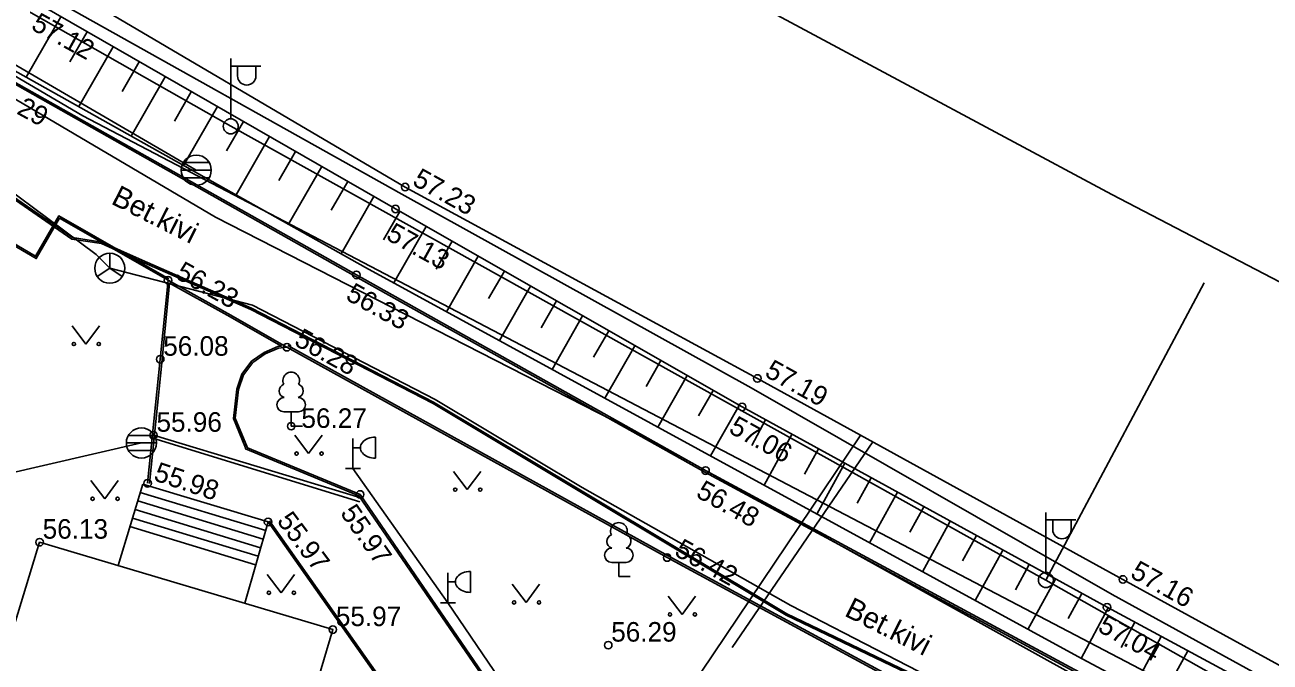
# Model space of a CAD drawing. Extents: x 542320 to 543602, y 6558748 to 6559969.
# Drawn here: x 543038.66 to 543080.07, y 6558919.22 to 6558940.4 of the extents above; entities that cross this region are included whole.
import ezdxf

# ---------------------------------------------------------------- set-up
doc = ezdxf.new("R2010")
doc.units = 0
for name, color, linetype in [('HALJASTUS', 7, 'Continuous'), ('HOONE', 7, 'Continuous'), ('HOONEDET', 7, 'Continuous'), ('KORGUS-EH2000', 7, 'Continuous'), ('KTRASS', 7, 'Continuous'), ('mootpiir', 7, 'Continuous'), ('MPKAABEL', 7, 'Continuous'), ('MPOHULIIN', 7, 'Continuous'), ('PIIR', 7, 'Continuous'), ('POST', 7, 'Continuous'), ('PUU', 7, 'Continuous'), ('RELJEEF', 7, 'Continuous'), ('SIKAEV', 7, 'Continuous'), ('SITRASS', 7, 'Continuous'), ('SKKAEV', 7, 'Continuous'), ('SKTRASS', 7, 'Continuous'), ('TEE', 7, 'Continuous'), ('VTRASS', 7, 'Continuous')]:
    doc.layers.add(name, color=color, linetype=linetype)

# ---------------------------------------------------------------- blocks, each defined once
blk = doc.blocks.new('LEHTP1')
for p, q in [((0.48, 0.95), (-0.48, 0.95)), ((0, 0), (0, 0.95)), ((0.76, 0), (0, 0))]:
    blk.add_line(p, q)
for centre, radius, start, end in [((0, 3.04), 0.554, 332.5799, 207.4201), ((-0.34, 2.345), 0.465, 109.02174, 253.14154), ((0.34, 2.345), 0.465, 286.85082, 70.98591), ((-0.475, 1.425), 0.475, 90.0016, 269.3953), ((0.475, 1.425), 0.475, 270.6047, 89.9984)]:
    blk.add_arc(centre, radius, start, end)
blk = doc.blocks.new('KAABVA')
for p, q in [((0, 2), (0, 0)), ((1.5, 0.693), (1.5, 2.093))]:
    blk.add_line(p, q)
for points in [[(0.5, 1.393), (0, 1.393)], [(-0.5, 0), (0.5, 0)]]:
    blk.add_lwpolyline(points)
blk.add_ellipse((1.5, 1.393), major_axis=(1, 0), ratio=0.7, start_param=1.570796, end_param=4.712389)
blk = doc.blocks.new('SIKAEV')
for p, q in [((0, 1), (0, 0)), ((0, 0), (-0.83, -0.55)), ((0, 0), (0.83, -0.55))]:
    blk.add_line(p, q)
blk.add_circle((0, 0), 1)
blk = doc.blocks.new('REKAEV')
for p, q in [((-1, 0), (1, 0)), ((0.86, 0.5), (-0.86, 0.5)), ((0.86, -0.5), (-0.86, -0.5))]:
    blk.add_line(p, q)
blk.add_circle((0, 0), 1)
blk = doc.blocks.new('PUPOST')
blk.add_circle((0, 0), 0.5)
blk = doc.blocks.new('VAPOST')
for p, q in [((0, 0.5), (0, 4.5)), ((0, 4), (2, 4)), ((0.453, 3.358), (0.453, 4)), ((1.679, 3.358), (1.679, 4))]:
    blk.add_line(p, q)
blk.add_arc((1.066, 3.358), 0.613, 180, 0)
blk = doc.blocks.new('MURU')
for p, q in [((-0.927, 1.213), (0, 0)), ((0, 0), (0.891, 1.213))]:
    blk.add_line(p, q)
for centre in [(-0.802, 0), (0.856, 0)]:
    blk.add_circle(centre, 0.11)
blk = doc.blocks.new('RING02')
blk.add_circle((0, 0), 0.25)

msp = doc.modelspace()

# ---------------------------------------------------------------- linework, layer by layer
at = {"layer": 'HOONE'}
msp.add_lwpolyline([(543034.683, 6558908.573), (543039.145, 6558923.204), (543048.898, 6558920.298), (543046.148, 6558911.034), (543052.456, 6558904.09), (543051.993, 6558903.334), (543059.743, 6558898.897), (543060.252, 6558899.636), (543066.159, 6558898.365), (543069.065, 6558900.487), (543081.93, 6558897.713), (543079.788, 6558887.775), (543071.384, 6558889.615), (543068.481, 6558887.445), (543058.412, 6558889.575), (543048.599, 6558888.632), (543044.558, 6558897.817)], close=True, dxfattribs=at)
at = {"layer": 'HOONEDET'}
for points in [[(543042.579, 6558925.135), (543041.755, 6558922.425)], [(543045.965, 6558921.176), (543046.742, 6558923.877), (543042.579, 6558925.135)], [(543046.582, 6558923.305), (543042.408, 6558924.574)], [(543046.668, 6558923.588), (543042.494, 6558924.857)], [(543046.496, 6558923.022), (543042.322, 6558924.291)], [(543046.324, 6558922.456), (543042.15, 6558923.725)], [(543046.41, 6558922.739), (543042.236, 6558924.008)]]:
    msp.add_lwpolyline(points, dxfattribs=at)
at = {"layer": 'KTRASS'}
msp.add_lwpolyline([(543046.435, 6558911.953), (543058.296, 6558914.646), (543066.44, 6558926.74)], dxfattribs=at)
at = {"layer": 'mootpiir'}
msp.add_lwpolyline([(543041.705, 6558842.986), (543026.57, 6558857.521), (543021.178, 6558871.989), (543014.73, 6558888.797), (543010.556, 6558896.706), (543004.564, 6558907.11), (542998.316, 6558921.614), (543000.462, 6558938.213), (543007.664, 6558949.977), (543004.131, 6558955.194), (543005.558, 6558957.946), (543018.426, 6558954.012), (543033.202, 6558945.57), (543039.476, 6558941.983), (543051.303, 6558935.01), (543063.018, 6558928.648), (543075.179, 6558921.966), (543087.717, 6558915.09), (543097.044, 6558910.296), (543101.236, 6558907.88), (543109.903, 6558904.892), (543122.322, 6558898.427)], dxfattribs=at)
at = {"layer": 'MPKAABEL'}
msp.add_lwpolyline([(543081.761, 6558896.926), (543082.099, 6558896.873), (543082.395, 6558897.034), (543085.057, 6558906.769), (543079.727, 6558907.382), (543074.242, 6558908.071), (543068.825, 6558908.727), (543063.367, 6558909.397), (543058.921, 6558912.202), (543055.778, 6558916.692), (543052.723, 6558921.189), (543049.567, 6558925.65)], dxfattribs=at)
at = {"layer": 'MPOHULIIN'}
for points in [[(543099.403, 6558906.806), (543072.616, 6558921.947), (543045.501, 6558937.03), (543017.777, 6558952.769), (543011.701, 6558956.054)], [(543072.616, 6558921.947), (543077.879, 6558931.822)]]:
    msp.add_lwpolyline(points, dxfattribs=at)
at = {"layer": 'PIIR'}
for points in [[(543133.64, 6558888.72), (543040.58, 6558937.38), (543035.44, 6558940.39), (542997.88, 6558962.4), (542987.35, 6558968.48), (542985.46, 6558965.33), (542959.34, 6558980.79), (542961.33, 6558984.1), (542942.14, 6558992.15), (542929.74, 6558997.94), (542900.76, 6559010.27), (542901.6, 6559029.9)], [(542901.6, 6559029.9), (542917.01, 6559022.75), (542962.12, 6559001.91), (542973.99, 6558994.27), (542985.8, 6558986.59), (542988.44, 6558985.08), (543008.85, 6558971.63), (543009.57, 6558972.89), (543032.02, 6558958.19), (543053.45, 6558946.21), (543074.81, 6558934.76), (543108.64, 6558917.15), (543148.25, 6558900.44)], [(543035.44, 6558940.39), (543040.58, 6558937.38), (543133.64, 6558888.72), (543159.27, 6558882.37), (543180.35, 6558877.33), (543188.6, 6558877.87), (543138.85, 6558855), (543136.39, 6558853.9), (543124.53, 6558851.31), (543111.21, 6558848.45), (543108.75, 6558866.73), (543082.72, 6558864.15), (543047.4, 6558848.41), (543054.87, 6558832.91), (543045.52, 6558829.45), (543026.29, 6558871.02), (543014.78, 6558890.86), (543006.52, 6558905.62), (543035.44, 6558940.39)]]:
    msp.add_lwpolyline(points, dxfattribs=at)
at = {"layer": 'RELJEEF'}
for points in [[(543101.897, 6558904.434), (543099.403, 6558906.806), (543096.044, 6558909.437), (543087.206, 6558914.268), (543074.649, 6558921.041), (543062.51, 6558927.7), (543050.982, 6558934.283), (543039.149, 6558941.077)], [(543039.854, 6558940.672), (543038.7, 6558938.662)], [(543040.722, 6558940.174), (543040.147, 6558939.174)], [(543041.589, 6558939.676), (543040.445, 6558937.684)], [(543037.968, 6558939.072), (543049.987, 6558932.338), (543073.674, 6558919.4), (543086.307, 6558912.668), (543095.539, 6558907.795), (543101.897, 6558904.434)], [(543042.456, 6558939.178), (543041.887, 6558938.187)], [(543043.323, 6558938.68), (543042.19, 6558936.707)], [(543044.19, 6558938.182), (543043.626, 6558937.2)], [(543045.058, 6558937.684), (543043.935, 6558935.729)], [(543045.925, 6558937.187), (543045.366, 6558936.213)], [(543046.792, 6558936.689), (543045.68, 6558934.751)], [(543047.659, 6558936.191), (543047.106, 6558935.227)], [(543048.527, 6558935.693), (543047.425, 6558933.774)], [(543049.394, 6558935.195), (543048.845, 6558934.24)], [(543050.261, 6558934.697), (543049.17, 6558932.796)], [(543051.128, 6558934.199), (543050.588, 6558933.252)], [(543051.997, 6558933.703), (543050.925, 6558931.826)], [(543052.865, 6558933.208), (543052.334, 6558932.277)], [(543053.734, 6558932.712), (543052.68, 6558930.867)], [(543054.602, 6558932.216), (543054.08, 6558931.302)], [(543055.47, 6558931.72), (543054.436, 6558929.908)], [(543056.339, 6558931.224), (543055.826, 6558930.326)], [(543057.207, 6558930.728), (543056.191, 6558928.949)], [(543058.076, 6558930.232), (543057.572, 6558929.351)], [(543058.944, 6558929.736), (543057.947, 6558927.99)], [(543059.812, 6558929.241), (543059.318, 6558928.376)], [(543060.681, 6558928.745), (543059.702, 6558927.031)], [(543061.549, 6558928.249), (543061.065, 6558927.4)], [(543062.417, 6558927.753), (543061.458, 6558926.073)], [(543063.293, 6558927.27), (543062.829, 6558926.424)], [(543064.17, 6558926.789), (543063.242, 6558925.098)], [(543065.047, 6558926.308), (543064.583, 6558925.463)], [(543065.924, 6558925.827), (543064.997, 6558924.139)], [(543066.8, 6558925.347), (543066.338, 6558924.503)], [(543067.677, 6558924.866), (543066.753, 6558923.18)], [(543068.554, 6558924.385), (543068.092, 6558923.543)], [(543069.431, 6558923.904), (543068.508, 6558922.222)], [(543070.307, 6558923.423), (543069.846, 6558922.583)], [(543071.184, 6558922.942), (543070.263, 6558921.263)], [(543072.061, 6558922.461), (543071.601, 6558921.622)], [(543072.938, 6558921.98), (543072.018, 6558920.304)], [(543073.814, 6558921.499), (543073.355, 6558920.662)], [(543074.691, 6558921.018), (543073.786, 6558919.34)], [(543075.571, 6558920.544), (543075.12, 6558919.707)], [(543076.451, 6558920.069), (543075.551, 6558918.4)], [(543077.332, 6558919.594), (543076.883, 6558918.762)]]:
    msp.add_lwpolyline(points, dxfattribs=at)
at = {"layer": 'SITRASS'}
for points in [[(543005.218, 6558957.454), (543044.997, 6558934.01), (543059.196, 6558926.752), (543074.381, 6558918.33), (543088.205, 6558911.502)], [(543004.2, 6558955.333), (543036.371, 6558936.228), (543041.03, 6558932.77), (543041.478, 6558932.313)], [(543064.26, 6558899.01), (543071.81, 6558902.91), (543075.17, 6558904.48), (543076.76, 6558907.49), (543078.62, 6558910.61), (543079.63, 6558911.97), (543079.37, 6558912.8), (543070.45, 6558917.73), (543064, 6558920.82), (543057.14, 6558924.93), (543052.25, 6558927.86), (543046.19, 6558930.99), (543042.46, 6558932.62), (543041.21, 6558933.18), (543040.24, 6558933.33), (543036.74, 6558935.74), (543033.41, 6558937.8), (543027.38, 6558941.25), (543021.13, 6558945), (543014.59, 6558948.63), (543009.37, 6558951.53), (543004.894, 6558954.068)], [(543064.24, 6558899.05), (543071.79, 6558902.95), (543075.13, 6558904.52), (543076.72, 6558907.51), (543078.58, 6558910.64), (543079.57, 6558911.98), (543079.33, 6558912.77), (543070.43, 6558917.69), (543063.98, 6558920.78), (543057.11, 6558924.89), (543052.23, 6558927.82), (543046.17, 6558930.94), (543042.44, 6558932.57), (543041.2, 6558933.13), (543040.22, 6558933.28), (543036.71, 6558935.7), (543033.38, 6558937.76), (543027.35, 6558941.21), (543021.1, 6558944.96), (543014.57, 6558948.59), (543009.35, 6558951.49), (543004.955, 6558953.977)], [(543121.901, 6558892.876), (543114.85, 6558896.99), (543111.27, 6558898.1), (543100.18, 6558902.69), (543091.12, 6558906.8), (543079.2, 6558913.04), (543070.5, 6558917.82), (543064.13, 6558921.1), (543057.19, 6558925.02), (543052.3, 6558927.95), (543046.23, 6558931.08), (543041.478, 6558932.313)]]:
    msp.add_lwpolyline(points, dxfattribs=at)
at = {"layer": 'SKTRASS'}
for points in [[(543031.415, 6558943.103), (543044.355, 6558935.572)], [(543042.907, 6558926.658), (543049.79, 6558924.543)], [(543042.932, 6558926.759), (543049.834, 6558924.682)], [(543036.293, 6558925.066), (543042.529, 6558926.503)]]:
    msp.add_lwpolyline(points, dxfattribs=at)
at = {"layer": 'TEE'}
for points in [[(543039.476, 6558941.983), (543051.303, 6558935.01), (543063.018, 6558928.648), (543075.179, 6558921.966), (543087.717, 6558915.09), (543097.044, 6558910.296), (543101.236, 6558907.88)], [(543100.939, 6558907.078), (543096.605, 6558909.676), (543087.4, 6558914.549), (543074.818, 6558921.463), (543062.815, 6558928.334), (543051.193, 6558934.777), (543039.337, 6558941.411)], [(543037.628, 6558938.816), (543049.652, 6558932.038), (543061.266, 6558925.532), (543073.39, 6558918.997), (543086.032, 6558912.226), (543093.141, 6558908.472), (543101.872, 6558904.379), (543104.96, 6558903.002), (543104.998, 6558903.893), (543104.894, 6558904.285), (543104.476, 6558905.119), (543104.056, 6558905.544), (543103.371, 6558905.967), (543101.022, 6558907.105), (543101.348, 6558907.702)], [(543037.657, 6558938.868), (543049.681, 6558932.09), (543061.295, 6558925.585), (543073.418, 6558919.05), (543086.06, 6558912.279), (543093.168, 6558908.526), (543101.897, 6558904.434), (543104.904, 6558903.093), (543104.938, 6558903.886), (543104.838, 6558904.264), (543104.427, 6558905.084), (543104.018, 6558905.497), (543103.342, 6558905.914), (543100.939, 6558907.078), (543101.295, 6558907.731)], [(543043.417, 6558931.913), (543039.802, 6558933.972), (543039.035, 6558932.631), (543035.374, 6558934.776), (543036.162, 6558936.141)], [(543043.447, 6558931.965), (543039.78, 6558934.054), (543039.013, 6558932.713), (543035.456, 6558934.798), (543036.214, 6558936.111)], [(543042.737, 6558925.163), (543043.156, 6558929.286), (543043.417, 6558931.913), (543045.41, 6558930.807), (543047.371, 6558929.686), (543047.085, 6558929.65), (543046.647, 6558929.461), (543046.236, 6558929.178), (543045.927, 6558928.765), (543045.764, 6558928.283), (543045.654, 6558927.323), (543046.056, 6558926.337), (543046.056, 6558926.337), (543049.803, 6558924.792), (543053.881, 6558918.848), (543057.844, 6558913.069), (543060.456, 6558909.35), (543068.387, 6558908.432), (543076.995, 6558907.406), (543085.705, 6558906.357), (543091.424, 6558905.658), (543091.756, 6558905.73)], [(543042.797, 6558925.157), (543043.216, 6558929.28), (543043.468, 6558931.816), (543045.381, 6558930.755), (543047.185, 6558929.723), (543047.069, 6558929.708), (543046.618, 6558929.514), (543046.194, 6558929.222), (543045.873, 6558928.793), (543045.705, 6558928.296), (543045.593, 6558927.315), (543045.992, 6558926.336), (543045.997, 6558926.308), (543049.765, 6558924.741), (543053.832, 6558918.814), (543057.795, 6558913.035), (543060.422, 6558909.293), (543068.38, 6558908.372), (543076.988, 6558907.346), (543085.698, 6558906.297), (543091.427, 6558905.597), (543091.769, 6558905.671)], [(543100.579, 6558901.54), (543091.756, 6558905.73), (543084.794, 6558909.393), (543071.804, 6558916.315), (543060.017, 6558922.694), (543047.371, 6558929.686)], [(543100.605, 6558901.594), (543091.783, 6558905.784), (543084.822, 6558909.446), (543071.832, 6558916.368), (543060.046, 6558922.747), (543047.4, 6558929.739)], [(543049.646, 6558907.336), (543051.74, 6558909.197), (543053.266, 6558910.484), (543053.702, 6558910.97), (543053.925, 6558911.375), (543054.074, 6558911.85), (543054.14, 6558912.292), (543054.048, 6558913.041), (543053.814, 6558913.686), (543051.501, 6558917.137), (543046.742, 6558923.877)], [(543049.686, 6558907.291), (543051.779, 6558909.152), (543053.308, 6558910.441), (543053.751, 6558910.935), (543053.98, 6558911.351), (543054.133, 6558911.837), (543054.201, 6558912.291), (543054.107, 6558913.055), (543053.868, 6558913.713), (543051.55, 6558917.171), (543046.791, 6558923.912)]]:
    msp.add_lwpolyline(points, dxfattribs=at)
at = {"layer": 'VTRASS'}
msp.add_lwpolyline([(543062.184, 6558919.7), (543066.861, 6558926.536)], dxfattribs=at)

# ---------------------------------------------------------------- block references
at = {"layer": 'HALJASTUS', "xscale": 0.5, "yscale": 0.5}
for p in [(543040.686, 6558929.793), (543048.093, 6558926.152), (543053.37, 6558924.951), (543041.309, 6558924.647), (543047.174, 6558921.521), (543055.327, 6558921.201), (543060.513, 6558920.805)]:
    msp.add_blockref('MURU', p, dxfattribs=at)
at = {"layer": 'KORGUS-EH2000', "xscale": 0.5, "yscale": 0.5}
for p in [(543051.303, 6558935.01), (543050.982, 6558934.283), (543043.417, 6558931.913), (543049.681, 6558932.09), (543047.371, 6558929.686), (543043.156, 6558929.286), (543063.018, 6558928.648), (543062.51, 6558927.7), (543047.512, 6558927.061), (543042.932, 6558926.759), (543061.295, 6558925.585), (543042.737, 6558925.163), (543049.803, 6558924.792), (543046.742, 6558923.877), (543039.145, 6558923.204), (543060.017, 6558922.694), (543075.179, 6558921.966), (543074.649, 6558921.041), (543048.898, 6558920.298), (543058.057, 6558919.782)]:
    msp.add_blockref('RING02', p, dxfattribs=at)
at = {"layer": 'POST', "xscale": 0.5, "yscale": 0.5}
for name, p in [('VAPOST', (543045.501, 6558937.03)), ('PUPOST', (543045.501, 6558937.03)), ('KAABVA', (543049.567, 6558925.65)), ('VAPOST', (543072.616, 6558921.947)), ('KAABVA', (543052.723, 6558921.189)), ('PUPOST', (543072.616, 6558921.947))]:
    msp.add_blockref(name, p, dxfattribs=at)
at = {"layer": 'PUU', "xscale": 0.5, "yscale": 0.5}
for p in [(543047.512, 6558927.061), (543058.412, 6558922.059)]:
    msp.add_blockref('LEHTP1', p, dxfattribs=at)
at = {"layer": 'SIKAEV', "xscale": 0.5, "yscale": 0.5}
msp.add_blockref('SIKAEV', (543041.478, 6558932.313), dxfattribs=at)
at = {"layer": 'SKKAEV', "xscale": 0.5, "yscale": 0.5}
for p in [(543044.355, 6558935.572), (543042.529, 6558926.503)]:
    msp.add_blockref('REKAEV', p, dxfattribs=at)

# ---------------------------------------------------------------- texts
at = {"layer": 'KORGUS-EH2000'}
for s, rotation, p in [('57.12', 331.0431, (543038.826, 6558940.27)), ('56.29', 331.4005, (543037.288, 6558938.044)), ('57.23', 331.0431, (543051.508, 6558935.1)), ('57.13', 331.0431, (543050.632, 6558933.288)), ('56.23', 331.0431, (543043.622, 6558932.003)), ('56.33', 331.0431, (543049.291, 6558931.289)), ('56.28', 331.0431, (543047.576, 6558929.776)), ('57.19', 331.0431, (543063.223, 6558928.738)), ('57.06', 331.0431, (543062.031, 6558926.866)), ('55.98', 341.5638, (543042.906, 6558925.269)), ('56.48', 331.0431, (543060.94, 6558924.727)), ('55.97', 304.8629, (543049.124, 6558924.172)), ('55.97', 306.9728, (543047.015, 6558923.907)), ('56.42', 331.0431, (543060.222, 6558922.784)), ('57.16', 331.0431, (543075.384, 6558922.056)), ('57.04', 331.0431, (543074.304, 6558920.262))]:
    msp.add_text(s, height=0.65, rotation=rotation, dxfattribs=at).set_placement(p)
for s, p in [('56.08', (543043.256, 6558929.403)), ('55.96', (543043.032, 6558926.876)), ('56.27', (543047.853, 6558927.005)), ('56.13', (543039.245, 6558923.321)), ('55.97', (543048.998, 6558920.415)), ('56.29', (543058.157, 6558919.899))]:
    msp.add_text(s, height=0.65, dxfattribs=at).set_placement(p)
at = {"layer": 'TEE'}
for p in [(543041.49, 6558934.47), (543065.879, 6558920.772)]:
    msp.add_text('Bet.kivi', height=0.7, rotation=333.1699, dxfattribs=at).set_placement(p)

doc.saveas('drawing.dxf')
